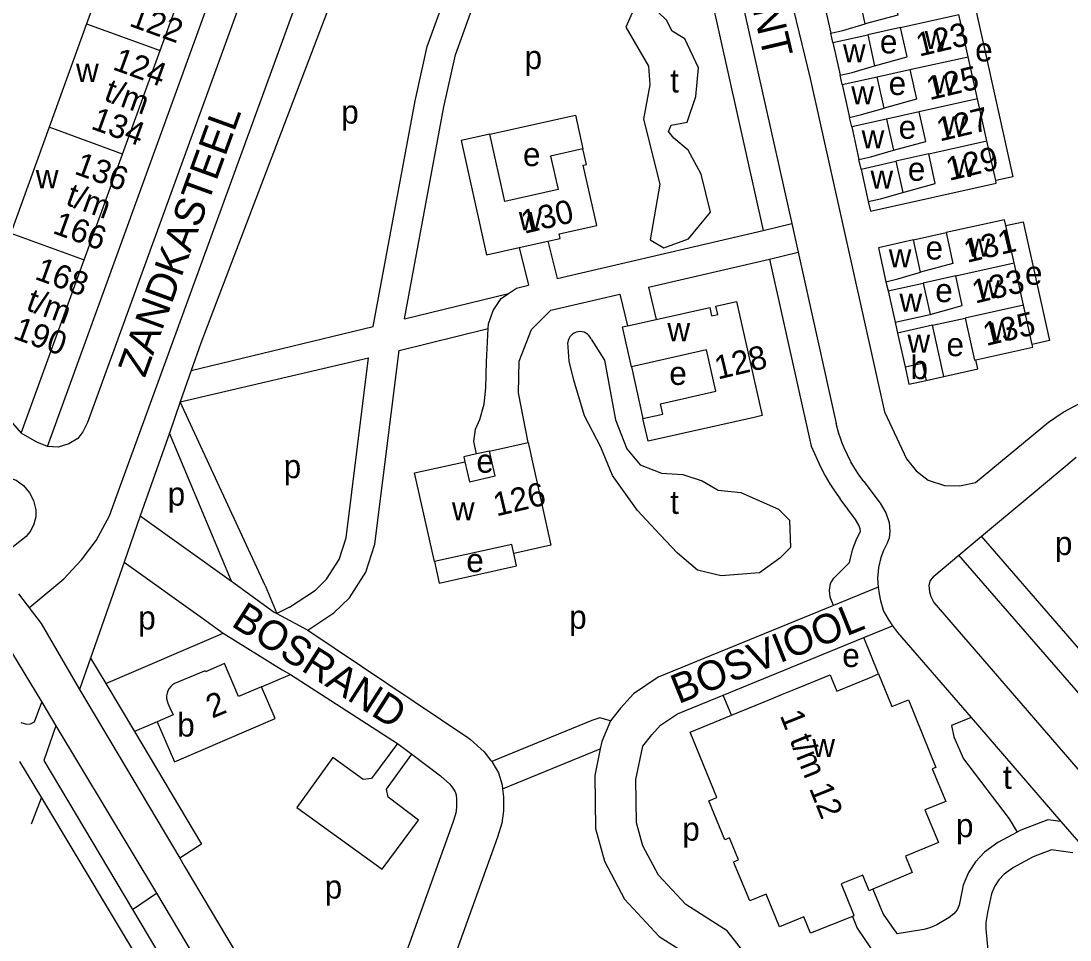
# Model space of a CAD drawing. Extents: x 155854 to 157362, y 383621 to 384685.
# Drawn here: x 156666.3 to 156844.9, y 383820.5 to 383977 of the extents above; entities that cross this region are included whole.
import ezdxf

# ---------------------------------------------------------------- set-up
doc = ezdxf.new("R2010")
doc.units = 0
for name, color, linetype in [('BLT_Basislijn', 7, 'Continuous'), ('BLT_Bebouwing', 7, 'Continuous'), ('BLT_Centroide', 7, 'Continuous'), ('BLT_Huisnummer', 7, 'Continuous'), ('BLT_Huisnummer_ tussenligend', 7, 'Continuous'), ('BLT_Huisnummer_reeks', 7, 'Continuous'), ('BLT_Onderverdeling_panden', 7, 'Continuous'), ('BLT_Straatnaam', 7, 'Continuous'), ('BLT_Vlakafsluiter', 7, 'Continuous')]:
    doc.layers.add(name, color=color, linetype=linetype)

msp = doc.modelspace()

# ---------------------------------------------------------------- linework, layer by layer
at = {"layer": 'BLT_Basislijn'}
for p, q in [((156670.8, 383904.59), (156719.54, 384038.82)), ((156782.7, 384008.89), (156797.51, 383942.52)), ((156777.89, 384007.5), (156792.64, 383941.38)), ((156793.56, 383996.39), (156800.68, 383967.21)), ((156718.76, 383979.48), (156699.07, 383927.86)), ((156800.68, 383967.21), (156813.31, 383910.5)), ((156792.64, 383941.38), (156797.51, 383942.52)), ((156757.56, 383933.17), (156792.64, 383941.38)), ((156818.24, 383939.75), (156823.82, 383940.99)), ((156751.12, 383938.46), (156752.69, 383932.03)), ((156756, 383939.55), (156757.56, 383933.17)), ((156773.12, 383931.68), (156793.73, 383936.5)), ((156793.73, 383936.5), (156798.6, 383937.64)), ((156793.73, 383936.5), (156800.83, 383904.65)), ((156798.6, 383937.64), (156805.1, 383908.47)), ((156773.12, 383931.68), (156774.43, 383926.22)), ((156731.57, 383926.31), (156749.29, 383930.65)), ((156768.25, 383930.54), (156769.55, 383925.13)), ((156699.07, 383927.86), (156696.9, 383922.16)), ((156695.27, 383917.53), (156726.24, 383925.01)), ((156730.64, 383920.93), (156745.84, 383924.66)), ((156696.9, 383922.16), (156695.27, 383917.53)), ((156693.39, 383912.16), (156725.44, 383919.66)), ((156695.27, 383917.53), (156693.39, 383912.16)), ((156770.21, 383918.15), (156772.19, 383909.33)), ((156693.39, 383912.16), (156691.53, 383906.84)), ((156707.85, 383880.92), (156693.39, 383912.16)), ((156813.31, 383910.5), (156817.06, 383902.46)), ((156828.82, 383898.46), (156841.22, 383908.74)), ((156691.53, 383906.84), (156686.59, 383892.76)), ((156702.12, 383881.65), (156691.53, 383906.84)), ((156746.05, 383903.78), (156743.82, 383903.3)), ((156838.28, 383896.36), (156845.93, 383902.77)), ((156829.83, 383889.28), (156838.28, 383896.36)), ((156686.59, 383892.76), (156683.83, 383884.89)), ((156686.59, 383892.76), (156702.12, 383881.65)), ((156826, 383886.06), (156829.83, 383889.28)), ((156885.98, 383824.5), (156829.83, 383889.28)), ((156683.83, 383884.89), (156678.1, 383868.53)), ((156821.72, 383882.48), (156826, 383886.06)), ((156880.7, 383822.96), (156826, 383886.06)), ((156707.85, 383880.92), (156709.84, 383876.13)), ((156812.22, 383880.61), (156804.66, 383877.52)), ((156711.98, 383877.23), (156709.84, 383876.13)), ((156709.84, 383876.13), (156715.09, 383873.29)), ((156809.78, 383872.05), (156814.66, 383874.05)), ((156680.69, 383864.2), (156700.69, 383872.8)), ((156785.85, 383862.24), (156809.78, 383872.05)), ((156812.32, 383865.86), (156809.78, 383872.05)), ((156663.7, 383871.15), (156669.79, 383861.04)), ((156678.1, 383868.53), (156676.22, 383863.18)), ((156678.1, 383868.53), (156680.69, 383864.2)), ((156707.24, 383863.67), (156712.18, 383865.78)), ((156676.22, 383863.18), (156693.3, 383834.45)), ((156680.69, 383864.2), (156685.57, 383856.03)), ((156787.26, 383858.83), (156785.85, 383862.24)), ((156689.45, 383857.7), (156685.57, 383856.03)), ((156766.66, 383857.88), (156765.16, 383854.34)), ((156828.08, 383858.42), (156843.37, 383840.73)), ((156672.2, 383857.03), (156670.14, 383851.13)), ((156672.2, 383857.03), (156689.36, 383828.51)), ((156730.39, 383853.98), (156732.82, 383852.17)), ((156742.39, 383855.02), (156742.83, 383854.7)), ((156765.16, 383854.34), (156764.91, 383853.11)), ((156748.29, 383846.31), (156764.91, 383853.11)), ((156666.02, 383850.93), (156669.74, 383844.74)), ((156746.25, 383851.19), (156746.47, 383850.91)), ((156668.06, 383840.33), (156669.74, 383844.74)), ((156843.37, 383840.73), (156848.31, 383835.02)), ((156685.25, 383825.74), (156689.36, 383828.51))]:
    msp.add_line(p, q, dxfattribs=at)
for points in [[(156667.8, 383877.2), (156673.57, 383882.06), (156676.58, 383885.26), (156679.07, 383888.56), (156681.33, 383892.78), (156682.61, 383896.21), (156709.45, 383969.83), (156748.63, 384077.57), (156768.01, 384131.23), (156804.03, 384230.53), (156827.74, 384296.18)], [(156719.54, 384038.82), (156723.34, 384034.44), (156677.59, 383908.65)], [(156731.57, 383926.31), (156738.3, 383962.42), (156740.24, 383971.29), (156744.34, 383982.65), (156749.98, 383996.23), (156753.83, 384003.53), (156759.03, 384011.61), (156762.67, 384016.52), (156765.06, 384019.24), (156767.59, 384021.17), (156770.37, 384022.72), (156773.72, 384023.9), (156774.21, 384023.99)], [(156726.24, 383925.01), (156733.4, 383963.42), (156735.43, 383972.68), (156739.68, 383984.46), (156745.45, 383998.36), (156747.16, 384001.6)], [(156824.55, 383984.47), (156827.51, 383985.13), (156835.2, 383950.52), (156832.26, 383949.87)], [(156746.09, 383957.76), (156760.67, 383961.02), (156761.96, 383955.26)], [(156833.96, 383942.2), (156836.91, 383942.84), (156841.42, 383922.61), (156838.48, 383921.95)], [(156749.29, 383930.65), (156750.63, 383931.55), (156752.69, 383932.03)], [(156745.84, 383924.66), (156745.89, 383925.46), (156746.7, 383927.75), (156748.03, 383929.79), (156749.29, 383930.65)], [(156752.61, 383905.23), (156750.97, 383913.74), (156751.09, 383919.09), (156753.19, 383924.5), (156756.51, 383927.79), (156768.25, 383930.54)], [(156743.82, 383903.3), (156743.36, 383905.45), (156743.65, 383907.52), (156744.4, 383909.19), (156745.15, 383911.76), (156745.4, 383914.55), (156745.53, 383918.97), (156745.84, 383924.66)], [(156763.36, 383922.88), (156765.65, 383919.25), (156767.52, 383909.13), (156769.43, 383904.2), (156771.73, 383901.47), (156775.37, 383900.02), (156779, 383899.81), (156782.24, 383898.75), (156785.01, 383897.13), (156788.87, 383896.74), (156795.24, 383893.9), (156797.13, 383892.01), (156797.3, 383887.37), (156795.49, 383885.57), (156792.05, 383883.07), (156785.52, 383882.56), (156781.48, 383883.5), (156778.04, 383886.43), (156775.12, 383889.52), (156771.25, 383893.65), (156767.02, 383899.62), (156765, 383904.48), (156762.21, 383909.78), (156760.39, 383915.86), (156759.64, 383919.09), (156759.41, 383922.26)], [(156715.09, 383873.29), (156719.56, 383876.24), (156722.21, 383878.83), (156725.01, 383883.19), (156726.52, 383887.95), (156730.64, 383920.93)], [(156711.98, 383877.23), (156716.4, 383880.14), (156718.31, 383882.01), (156720.45, 383885.34), (156721.62, 383889.02), (156725.44, 383919.66)], [(156823.43, 383916.51), (156829.2, 383917.79), (156828.86, 383919.32)], [(156841.22, 383908.74), (156843.72, 383910.43), (156846.39, 383911.85), (156849.22, 383912.99), (156852.13, 383913.81), (156855.1, 383914.32)], [(156648.34, 383907.58), (156650.73, 383905.27), (156653.33, 383903.36), (156656.02, 383902.06), (156660.22, 383900.56), (156665.45, 383898.82), (156666.67, 383897.95), (156667.72, 383896.7), (156668.42, 383895.38), (156668.79, 383893.79), (156668.78, 383892.59), (156668.46, 383891.35), (156667.94, 383890.28), (156667.16, 383889.25), (156661.72, 383884.98)], [(156677.59, 383908.65), (156676.81, 383907.08), (156675.92, 383905.95), (156674.44, 383905.04), (156672.61, 383904.47), (156670.8, 383904.59)], [(156806.45, 383904.37), (156806.13, 383905.17), (156805.83, 383905.98), (156805.56, 383906.8), (156805.32, 383907.63), (156805.1, 383908.47)], [(156670.8, 383904.59), (156670.78, 383904.59), (156668.95, 383905.29), (156666.3, 383906.85)], [(156800.83, 383904.65), (156802.5, 383900.98), (156803.23, 383899.57), (156804.03, 383898.21), (156804.89, 383896.88), (156805.79, 383895.64)], [(156809.79, 383898.64), (156809.01, 383899.71), (156808.28, 383900.83), (156807.61, 383901.98), (156807, 383903.16), (156806.45, 383904.37)], [(156743.82, 383903.3), (156741.67, 383902.81), (156741.85, 383901.99)], [(156817.06, 383902.46), (156818.71, 383900.41), (156820.75, 383898.87), (156823.51, 383897.92), (156826.16, 383897.87), (156828.82, 383898.46)], [(156809.79, 383898.64), (156812.57, 383894.93), (156813.52, 383893.29), (156814.09, 383891.66), (156814.24, 383890.08), (156814.12, 383889), (156813.79, 383888.09)], [(156809.21, 383890.12), (156809.17, 383890.58), (156808.96, 383891.19), (156808.39, 383892.16), (156805.79, 383895.64)], [(156804.66, 383877.52), (156804.08, 383878.94), (156803.94, 383880.12), (156804.15, 383881.24), (156804.67, 383882.15), (156807.38, 383884.82), (156807.91, 383887.13), (156808.59, 383888.93), (156809.21, 383890.12)], [(156813.79, 383888.09), (156813.16, 383886.88), (156812.7, 383885.68), (156812.31, 383883.98), (156812.24, 383883.33)], [(156736.68, 383885.01), (156737.49, 383881.33), (156750.67, 383884.23), (156750.2, 383886.36)], [(156683.83, 383884.89), (156697.15, 383875.37), (156700.69, 383872.8)], [(156812.24, 383883.33), (156812.11, 383882.17), (156812.22, 383880.61)], [(156702.12, 383881.65), (156709.37, 383876.39), (156709.84, 383876.13)], [(156821.72, 383882.48), (156821.08, 383881.75), (156820.87, 383880.9), (156820.96, 383879.8), (156821.2, 383879.05), (156821.71, 383878.01), (156874.06, 383817.46)], [(156665.87, 383879.49), (156669.71, 383874.45), (156676.22, 383863.18)], [(156812.22, 383880.61), (156812.39, 383879.48), (156812.62, 383878.31), (156812.68, 383878.11)], [(156804.66, 383877.52), (156774.77, 383865.27), (156770.57, 383862.45), (156768.38, 383860.04), (156766.66, 383857.88)], [(156812.68, 383878.11), (156813.15, 383876.54), (156813.95, 383875.16), (156814.66, 383874.05)], [(156814.66, 383874.05), (156815.55, 383872.91), (156828.08, 383858.42)], [(156700.69, 383872.8), (156710.77, 383866.52), (156712.18, 383865.78)], [(156715.09, 383873.29), (156742.39, 383855.02)], [(156712.18, 383865.78), (156730.39, 383853.98)], [(156772.14, 383853.53), (156773.71, 383855.5), (156775.17, 383857.11), (156778.08, 383859.06), (156785.85, 383862.24)], [(156666.23, 383857.56), (156667.18, 383857.27), (156667.87, 383857.35), (156668.55, 383857.69), (156669.79, 383861.04)], [(156669.79, 383861.04), (156672.2, 383857.03)], [(156766.66, 383857.88), (156764.83, 383858.4), (156763.46, 383857.92), (156746.47, 383850.91)], [(156828.08, 383858.42), (156824.7, 383857.08), (156825.12, 383855.13), (156826.77, 383851.37), (156834.57, 383841.17), (156835.9, 383838.92)], [(156685.57, 383856.03), (156697.03, 383836.87), (156693.3, 383834.45)], [(156730.39, 383853.98), (156725.97, 383848.02), (156724.52, 383847.87), (156719.4, 383851.61), (156713.25, 383843.12), (156727.77, 383832.59), (156733.98, 383840.97), (156728.79, 383844.87), (156728.51, 383846.22), (156732.82, 383852.17)], [(156742.83, 383854.7), (156745.13, 383852.58), (156746.25, 383851.19)], [(156732.82, 383852.17), (156737.72, 383848.52), (156739.28, 383847.09), (156739.83, 383846.41), (156740.19, 383845.78), (156740.36, 383845.24), (156740.46, 383844.44), (156740.46, 383843.17), (156740.3, 383842.16), (156739.83, 383840.54), (156725.03, 383799.46), (156724.51, 383796.74), (156724.35, 383793.96), (156724.44, 383791.46)], [(156764.91, 383853.11), (156763.97, 383848.58), (156764.08, 383839.51), (156765.63, 383833.98), (156769.06, 383827.51), (156774.96, 383821.13), (156781.76, 383816.85), (156785.37, 383812.2), (156791.91, 383796.82), (156792.72, 383792.85), (156791.38, 383790.1), (156762.77, 383773.14)], [(156791.44, 383815.79), (156786.53, 383822.12), (156779.48, 383826.56), (156774.82, 383831.59), (156772.17, 383836.59), (156771.07, 383840.52), (156770.98, 383847.9), (156772.14, 383853.53)], [(156670.14, 383851.13), (156685.25, 383825.74)], [(156746.47, 383850.91), (156747.56, 383849), (156748.21, 383846.94), (156748.29, 383846.31)], [(156748.29, 383846.31), (156748.46, 383844.93), (156748.46, 383842.56), (156748.13, 383840.42), (156747.44, 383838.06), (156732.77, 383797.34), (156732.47, 383795.75), (156732.36, 383793.86), (156732.41, 383792.39), (156732.74, 383790.75), (156733.23, 383788.77), (156734, 383787.18), (156735.02, 383785.34), (156776.38, 383714.97)], [(156669.74, 383844.74), (156688.13, 383814.06)], [(156843.37, 383840.73), (156841.16, 383841.02), (156836.54, 383839.27), (156835.9, 383838.92)], [(156835.9, 383838.92), (156832.63, 383837.12), (156830.37, 383835.51), (156828.82, 383833.85), (156827.64, 383832.05), (156826.73, 383829.9), (156826.02, 383826.46), (156825.69, 383825.67), (156825.14, 383825.02), (156824.32, 383824.37), (156822.23, 383823.14), (156821.03, 383822.59), (156820.02, 383822.34), (156815.49, 383821.62)], [(156693.3, 383834.45), (156694.05, 383833.18), (156722.37, 383785.59)], [(156845.38, 383835.41), (156841.75, 383835.9), (156838.64, 383834.71), (156835.29, 383832.88), (156833.68, 383831.74), (156832.77, 383830.76), (156832.07, 383829.68), (156831.53, 383828.4), (156830.87, 383825.24)], [(156811.33, 383829.19), (156813.11, 383824.92), (156814.88, 383822.31), (156815.49, 383821.62)], [(156689.36, 383828.51), (156736.06, 383749.98), (156767.78, 383696.45)], [(156685.25, 383825.74), (156707.5, 383788.33), (156730.26, 383749.98), (156750.05, 383716.65), (156763.06, 383694.74)], [(156807.84, 383824.56), (156808.69, 383822.53), (156810.93, 383819.23), (156811.5, 383818.59)], [(156830.87, 383825.24), (156830.58, 383823.55), (156830.56, 383822.42), (156831.09, 383816.97), (156831.01, 383815.31), (156830.72, 383813.59), (156829.68, 383811), (156826.77, 383805.21), (156826.42, 383804.3), (156826.24, 383803.45), (156826.22, 383802.56), (156826.32, 383801.7), (156826.71, 383800.54), (156827.73, 383798.79), (156828.81, 383797.37), (156830.14, 383796.27), (156831.58, 383796.27), (156833.13, 383796.74)]]:
    msp.add_lwpolyline(points, dxfattribs=at)
msp.add_lwpolyline([(156774.7, 383978.59), (156770.37, 383978.42), (156769.26, 383975.96), (156773.11, 383969.34), (156773.36, 383966.15), (156772.29, 383960.33), (156775.03, 383949.23), (156773.42, 383939.79), (156775.72, 383938.38), (156779.95, 383939.93), (156783.67, 383944.5), (156782.1, 383950.93), (156779.9, 383955.05), (156777.47, 383957.09), (156776.54, 383958.21), (156776.98, 383959.32), (156779.7, 383959.8), (156781.18, 383964.17), (156781.63, 383969.04), (156779.33, 383973.99), (156777.15, 383975.3), (156776.22, 383977.18)], close=True, dxfattribs=at)
msp.add_arc((156761.46, 383922.08), 2.06, 22.8954, 174.8234, dxfattribs=at)
at = {"layer": 'BLT_Bebouwing'}
for p, q in [((156683.92, 383994.35), (156677.45, 383976.53)), ((156689.95, 383971.99), (156696.42, 383989.81)), ((156677.45, 383976.53), (156671.05, 383958.93)), ((156804.52, 383973.35), (156804.17, 383974.96)), ((156683.56, 383954.38), (156689.95, 383971.99)), ((156806.11, 383966.21), (156805.76, 383967.79)), ((156807.73, 383959), (156807.36, 383960.62)), ((156671.05, 383958.93), (156664.51, 383940.92)), ((156677.02, 383936.37), (156683.56, 383954.38)), ((156809.32, 383951.82), (156808.96, 383953.43)), ((156751.12, 383938.46), (156756, 383939.55)), ((156666.3, 383906.85), (156677.02, 383936.37)), ((156813.92, 383931.06), (156815.12, 383925.75)), ((156769.55, 383925.13), (156774.43, 383926.22)), ((156815.12, 383925.75), (156815.53, 383923.89)), ((156651.65, 383923.72), (156666.3, 383906.85)), ((156746.05, 383903.78), (156752.61, 383905.23)), ((156697.62, 383866.38), (156692.43, 383864.22))]:
    msp.add_line(p, q, dxfattribs=at)
for points in [[(156814.4, 383983.3), (156815.57, 383978.05), (156810.05, 383976.55)], [(156810.05, 383976.55), (156808.82, 383982.06)], [(156802.88, 383980.74), (156804.17, 383974.96)], [(156827.56, 383970.95), (156825.97, 383978.13)], [(156816.04, 383975.91), (156810.47, 383974.67)], [(156811.64, 383969.41), (156817.16, 383970.92), (156816.04, 383975.91)], [(156810.47, 383974.67), (156811.64, 383969.41)], [(156804.52, 383973.35), (156805.76, 383967.79)], [(156829.17, 383963.78), (156827.56, 383970.95)], [(156812.06, 383967.54), (156817.63, 383968.78)], [(156817.63, 383968.78), (156818.77, 383963.7), (156813.25, 383962.2)], [(156813.25, 383962.2), (156812.06, 383967.54)], [(156806.11, 383966.21), (156807.36, 383960.62)], [(156830.76, 383956.6), (156829.17, 383963.78)], [(156819.24, 383961.56), (156813.67, 383960.32)], [(156814.85, 383955.02), (156820.36, 383956.53), (156819.24, 383961.56)], [(156813.67, 383960.32), (156814.85, 383955.02)], [(156746.09, 383957.76), (156741.24, 383956.68), (156745.55, 383937.22), (156751.12, 383938.46)], [(156761.96, 383955.26), (156756.46, 383954.04), (156757.73, 383948.32), (156748.64, 383946.28), (156746.09, 383957.76)], [(156807.73, 383959), (156808.96, 383953.43)], [(156832.26, 383949.87), (156830.76, 383956.6)], [(156756, 383939.55), (156758.08, 383940.02), (156757.93, 383940.77), (156764.31, 383942.2), (156762.03, 383952.46), (156762.55, 383952.57), (156761.96, 383955.26)], [(156820.84, 383954.39), (156815.27, 383953.15)], [(156816.45, 383947.85), (156821.96, 383949.36), (156820.84, 383954.39)], [(156815.27, 383953.15), (156816.45, 383947.85)], [(156809.32, 383951.82), (156810.56, 383946.27)], [(156810.56, 383946.27), (156810.92, 383944.65), (156832.36, 383949.43), (156832.26, 383949.87)], [(156833.96, 383942.2), (156833.74, 383943.19), (156823.82, 383940.99)], [(156835.38, 383935.83), (156833.96, 383942.2)], [(156818.24, 383939.75), (156812.31, 383938.43), (156813.56, 383932.64)], [(156819.47, 383934.24), (156818.24, 383939.75)], [(156823.82, 383940.99), (156824.98, 383935.75), (156819.47, 383934.24)], [(156836.98, 383928.66), (156835.38, 383935.83)], [(156813.56, 383932.64), (156813.92, 383931.06)], [(156825.45, 383933.62), (156819.89, 383932.39)], [(156821.1, 383927.08), (156826.57, 383928.57), (156825.45, 383933.62)], [(156819.89, 383932.39), (156821.1, 383927.08)], [(156774.43, 383926.22), (156783.56, 383928.26), (156783.88, 383926.82), (156783.88, 383926.82), (156784.93, 383927.06), (156784.61, 383928.49), (156788.14, 383929.28), (156792.51, 383909.83), (156791.13, 383909.52), (156773.05, 383905.46), (156772.19, 383909.33)], [(156838.48, 383921.95), (156836.98, 383928.66)], [(156821.52, 383925.22), (156827.04, 383926.44)], [(156827.04, 383926.44), (156828.65, 383919.28), (156828.86, 383919.32)], [(156770.21, 383918.15), (156768.7, 383924.94), (156769.55, 383925.13)], [(156815.53, 383923.89), (156816.82, 383918.13)], [(156823.43, 383916.51), (156821.52, 383925.22)], [(156828.86, 383919.32), (156838.59, 383921.49), (156838.48, 383921.95)], [(156772.19, 383909.33), (156775.56, 383910.08), (156775.17, 383911.85), (156784.61, 383913.98), (156783.02, 383921.04), (156770.21, 383918.15)], [(156816.82, 383918.13), (156817.47, 383915.2), (156820.4, 383915.84)], [(156820.4, 383915.84), (156823.43, 383916.51)], [(156752.61, 383905.23), (156756.51, 383887.77), (156750.2, 383886.36)], [(156741.85, 383901.99), (156742.62, 383898.58), (156747, 383899.56), (156746.05, 383903.78)], [(156736.68, 383885.01), (156733.29, 383900.1), (156741.85, 383901.99)], [(156750.2, 383886.36), (156749.86, 383887.91), (156736.68, 383885.01)], [(156691.26, 383860.89), (156691.61, 383860.06), (156692.18, 383858.88), (156689.45, 383857.7), (156692.39, 383850.89), (156709.55, 383858.26), (156707.24, 383863.67), (156703.32, 383861.99), (156700.92, 383867.6), (156697.69, 383866.22), (156697.62, 383866.38)], [(156787.26, 383858.83), (156794.06, 383861.61), (156795.92, 383862.38), (156798.21, 383863.31), (156804.04, 383865.7), (156804.22, 383865.26), (156805.18, 383862.92), (156810.75, 383865.21), (156812.32, 383865.86)], [(156812.32, 383865.86), (156814.59, 383860.3), (156817.38, 383861.45), (156822.06, 383849.94), (156821.46, 383849.69), (156823.74, 383844.14), (156820.2, 383842.68), (156822.5, 383837.14), (156816.87, 383834.83), (156818.05, 383832.05), (156811.33, 383829.19)], [(156692.43, 383864.22), (156692.09, 383863.99), (156691.78, 383863.71), (156691.51, 383863.37), (156691.3, 383862.98), (156691.15, 383862.56), (156691.07, 383862.12), (156691.07, 383861.68), (156691.14, 383861.27), (156691.26, 383860.89)], [(156807.84, 383824.56), (156800.74, 383821.68), (156799.6, 383824.5), (156795.42, 383822.79), (156793.14, 383828.33), (156790.36, 383827.19), (156787.63, 383833.86), (156788.46, 383834.21), (156786.93, 383837.92), (156786.1, 383837.58), (156783.38, 383844.24), (156784.76, 383844.81), (156780.2, 383855.94), (156787.26, 383858.83)], [(156811.33, 383829.19), (156811.06, 383829.07), (156810.69, 383828.93), (156809.62, 383831.57), (156805.93, 383830.08), (156807.97, 383825.04), (156808.12, 383824.67), (156807.84, 383824.56)]]:
    msp.add_lwpolyline(points, dxfattribs=at)
at = {"layer": 'BLT_Onderverdeling_panden'}
for p, q in [((156816.04, 383975.91), (156825.97, 383978.13)), ((156677.45, 383976.53), (156689.95, 383971.99)), ((156806.22, 383975.42), (156810.05, 383976.55)), ((156804.52, 383973.35), (156810.47, 383974.67)), ((156817.63, 383968.78), (156827.56, 383970.95)), ((156807.81, 383968.25), (156811.64, 383969.41)), ((156806.11, 383966.21), (156812.06, 383967.54)), ((156829.17, 383963.78), (156819.24, 383961.56)), ((156809.41, 383961.08), (156813.25, 383962.2)), ((156813.67, 383960.32), (156807.73, 383959)), ((156683.56, 383954.38), (156671.05, 383958.93)), ((156820.84, 383954.39), (156830.76, 383956.6)), ((156811, 383953.89), (156814.85, 383955.02)), ((156809.32, 383951.82), (156815.27, 383953.15)), ((156812.61, 383946.72), (156816.45, 383947.85)), ((156664.51, 383940.92), (156677.02, 383936.37)), ((156825.45, 383933.62), (156835.38, 383935.83)), ((156815.61, 383933.1), (156819.47, 383934.24)), ((156813.92, 383931.06), (156819.89, 383932.39)), ((156836.98, 383928.66), (156827.04, 383926.44)), ((156815.12, 383925.75), (156821.1, 383927.08)), ((156821.52, 383925.22), (156815.53, 383923.89))]:
    msp.add_line(p, q, dxfattribs=at)
for points in [[(156804.17, 383974.96), (156806.22, 383975.42)], [(156805.76, 383967.79), (156807.81, 383968.25)], [(156807.36, 383960.62), (156809.41, 383961.08)], [(156808.96, 383953.43), (156811, 383953.89)], [(156810.56, 383946.27), (156812.61, 383946.72)], [(156813.56, 383932.64), (156815.61, 383933.1)], [(156816.82, 383918.13), (156819.75, 383918.78), (156820.4, 383915.84)]]:
    msp.add_lwpolyline(points, dxfattribs=at)
at = {"layer": 'BLT_Vlakafsluiter'}
msp.add_line((156797.51, 383942.52), (156798.6, 383937.64), dxfattribs=at)

# ---------------------------------------------------------------- texts
at = {"layer": 'BLT_Centroide'}
for s, p in [('e', (156812.53, 383971.51)), ('w', (156820.17, 383972.24)), ('p', (156752.03, 383968.85)), ('w', (156806.25, 383970.01)), ('e', (156828.76, 383970.15)), ('w', (156675.64, 383966.67)), ('t', (156776.83, 383964.86)), ('e', (156814.03, 383964.42)), ('w', (156821.63, 383964.69)), ('w', (156807.66, 383962.83)), ('p', (156720.81, 383959.56)), ('e', (156815.73, 383956.96)), ('w', (156823.24, 383957.7)), ('w', (156809.42, 383955.32)), ('e', (156751.76, 383952.32)), ('e', (156817.29, 383949.82)), ('w', (156824.96, 383950.47)), ('w', (156668.79, 383948.56)), ('w', (156810.93, 383948.5)), ('w', (156751.05, 383941.41)), ('w', (156827.45, 383936.91)), ('w', (156814.04, 383935.1)), ('e', (156820.31, 383936.41)), ('e', (156837.25, 383932.12)), ('w', (156829.09, 383929.78)), ('e', (156821.96, 383929.16)), ('w', (156815.87, 383927.52)), ('w', (156776.35, 383922.51)), ('w', (156831.37, 383922.59)), ('w', (156817.23, 383920.57)), ('e', (156823.88, 383919.95)), ('b', (156817.75, 383916.05)), ('e', (156776.67, 383915.06)), ('p', (156711.01, 383899.19)), ('e', (156743.82, 383900.11)), ('p', (156691.25, 383894.51)), ('t', (156776.83, 383893.09)), ('w', (156739.65, 383892)), ('p', (156842.34, 383886.1)), ('e', (156742.1, 383883.19)), ('p', (156686.24, 383873.42)), ('p', (156759.62, 383873.54)), ('e', (156806.13, 383867.02)), ('b', (156692.88, 383855.19)), ('w', (156801.03, 383851.69)), ('t', (156833.5, 383846.28)), ('p', (156778.89, 383837.46)), ('p', (156825.49, 383838.06)), ('p', (156717.99, 383827.6))]:
    msp.add_text(s, height=4, dxfattribs=at).set_placement(p)
at = {"layer": 'BLT_Huisnummer'}
for s, rotation, p in [('125', 13.3751, (156820.99, 383963.52)), ('129', 13.3751, (156824.32, 383949.79)), ('130', 13.3751, (156751.97, 383940.77)), ('131', 13.3751, (156827.36, 383935.83)), ('135', 13.3751, (156830.62, 383921.67)), ('128', 13.3751, (156784.92, 383915.96)), ('126', 13.3751, (156747.23, 383892.65)), ('2', 22.8127, (156698.82, 383858.22))]:
    msp.add_text(s, height=4, rotation=rotation, dxfattribs=at).set_placement(p)
at = {"layer": 'BLT_Huisnummer_ tussenligend'}
for s, p in [('123', (156819.21, 383970.94)), ('127', (156822.72, 383956.49)), ('133', (156828.74, 383928.89))]:
    msp.add_text(s, height=4, rotation=13.3751, dxfattribs=at).set_placement(p)
at = {"layer": 'BLT_Huisnummer_reeks'}
for s, rotation, p in [('122', 340.0266, (156684.52, 383976.25)), ('124', 340.0266, (156681.7, 383968.84)), ('t/m', 340.0266, (156680.21, 383963.57)), ('134', 340.0266, (156678, 383958.74)), ('136', 340.0266, (156675.18, 383951.06)), ('t/m', 340.0266, (156673.69, 383945.79)), ('166', 340.0266, (156671.48, 383940.96)), ('168', 340.0266, (156668.43, 383933.14)), ('t/m', 340.0266, (156666.94, 383927.87)), ('190', 340.0266, (156664.73, 383923.04)), ('1 t/m 12', 291.9241, (156795.44, 383858.79))]:
    msp.add_text(s, height=4, rotation=rotation, dxfattribs=at).set_placement(p)
at = {"layer": 'BLT_Straatnaam'}
for s, rotation, p in [('BOSFAZANT', 283.2822, (156783.67, 384009.43)), ('ZANDKASTEEL', 70.0435, (156687.35, 383916.14)), ('BOSRAND', 327.4425, (156701.88, 383874.13)), ('BOSVIOOL', 21.9998, (156778.24, 383860.68))]:
    msp.add_text(s, height=5, rotation=rotation, dxfattribs=at).set_placement(p)

doc.saveas('drawing.dxf')
